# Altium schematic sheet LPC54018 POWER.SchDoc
size A4; CheckedBy: 赵金生; Author: 伍伟业; CompanyName: 广州周立功单片机科技有限公司; DocumentNumber: 8; SheetNumber: 8A; SheetTotal: 19; PageSetup: Record=PageOptions|CenterHorizontal=True|CenterVertical=True|PrintScale=1.00|XCorrection=1.00|YCorrection=1.00|PrintKind=0|BorderSize=5000000|LeftOffset=0|BottomOffset=0|Orientation=2|PaperLength=1000|PaperWidth=1000|Scale=100|PaperSource=7|PrintQuality=600|MediaType=1|DitherType=10|PaperKind=A4|PrintScaleMode=1; DesignDate: 2017-3-16; CheckDate: 2017-3-16; SheetName: LPC54018 POWER; SheetVersion: V1.0; SheetDescription: LPC54018 POWER; ModifiedDate1: 2017/8/15; ModifiedContent1: 复位电路增加续流二极管D12
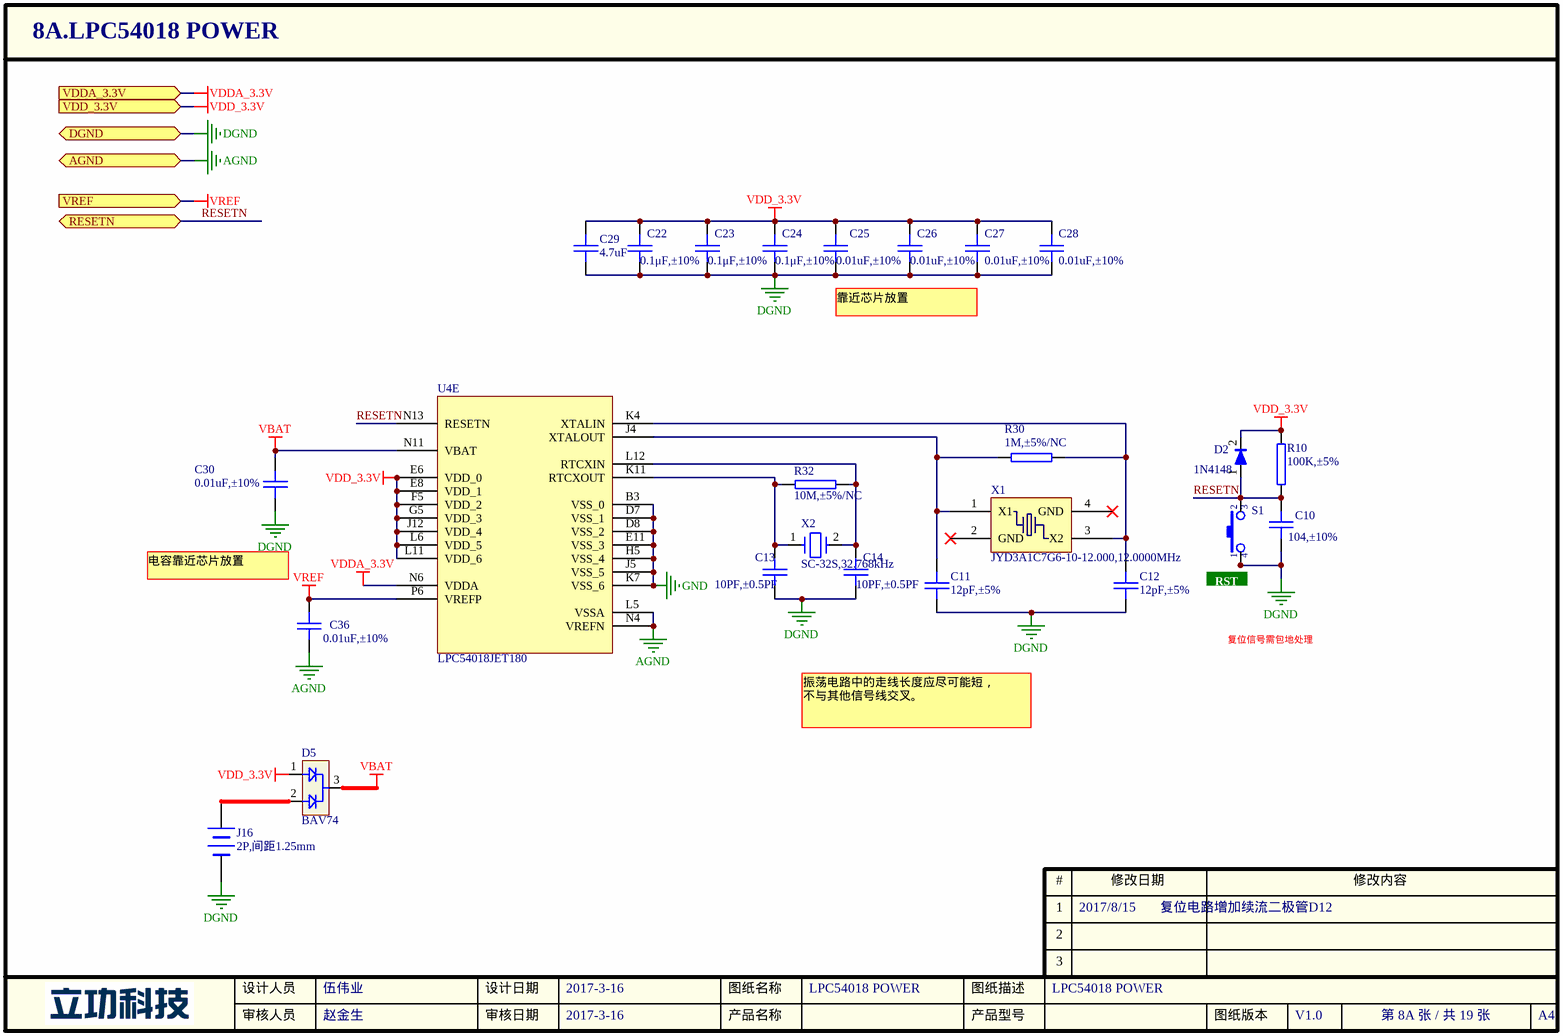
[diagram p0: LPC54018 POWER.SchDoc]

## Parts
C10  104,±10%  [0603C]
C11  12pF,±5%  [0402C]
C12  12pF,±5%  [0402C]
C13  10PF,±0.5PF  [0402C]
C14  10PF,±0.5PF  [0402C]
C22  0.1μF,±10%  [0402C]
C23  0.1μF,±10%  [0402C]
C24  0.1μF,±10%  [0402C]
C25  0.01uF,±10%  [0402C]
C26  0.01uF,±10%  [0402C]
C27  0.01uF,±10%  [0402C]
C28  0.01uF,±10%  [0402C]
C29  4.7uF  [0603CL]
C30  0.01uF,±10%  [0402C]
C36  0.01uF,±10%  [0402CL]
D2  1N4148  [SOD-323]
D5  BAV74  [SOT-23]
J16  value 2P,间距1.25mm  [FPC2-49T]  (hidden comment: BATTERY)
R10  100K,±5%  [0402R]
R30  1M,±5%/NC  [0402R]
R32  10M,±5%/NC  [0402R]
S1  TS0641-0501B,6×6×5.0mm  [KEY-6S]  (value not drawn)
U4  LPC54018JET180  [BGA180C80P14x14]  (part E of 5)
X1  JYD3A1C7G6-10-12.000,12.0000MHz  [OSCCC250X320X80-4N]
X2  SC-32S,32.768kHz  [XTAL320X150X90]

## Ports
AGND, DGND, RESETN (bidir), VDD_3.3V (in), VDDA_3.3V (in), VREF (in)

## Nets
AGND: C36.2 U4.L5(VSSA) U4.N4(VREFN) ; port AGND
DGND: C10.2 C11.2 C12.1 C13.2 C14.2 C22.2 C23.2 C24.2 C25.2 C26.2 C27.2 C28.2 C29.2 C30.2 J16.2(-) S1.1 S1.4 ; port DGND
GND: U4.B3(VSS_0) U4.D7(VSS_1) U4.D8(VSS_2) U4.E11(VSS_3) U4.H5(VSS_4) U4.J5(VSS_5) U4.K7(VSS_6)
VBAT: C30.1 D5.3(A) U4.N11(VBAT)
VDD_3.3V: C22.1 C23.1 C24.1 C25.1 C26.1 C27.1 C28.1 C29.1 D2.2 D5.1(D1) R10.2 U4.E6(VDD_0) U4.E8(VDD_1) U4.F5(VDD_2) U4.G5(VDD_3) U4.J12(VDD_4) U4.L6(VDD_5) U4.L11(VDD_6) ; port VDD_3.3V
VDDA_3.3V: U4.N6(VDDA) ; port VDDA_3.3V
VREF: C36.1 U4.P6(VREFP) ; port VREF
RESETN: C10.1 D2.1 R10.1 S1.2 S1.3 U4.N13(RESETN) ; port RESETN
NetC11_1: C11.1 R30.1 U4.J4(XTALOUT) X1.1(X1)
NetC12_2: C12.2 R30.2 U4.K4(XTALIN) X1.3(X2)
NetC13_1: C13.1 R32.1 U4.K11(RTCXOUT) X2.1
NetC14_1: C14.1 R32.2 U4.L12(RTCXIN) X2.2
NetD5_2: D5.2(D2) J16.1(+)

Not connected (* = marked no-connect by the designer): X1 2(GND)* 4(GND)*

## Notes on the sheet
- 靠近芯片放置
- 电容靠近芯片放置
- (near S1) RST
- 复位信号需包地处理
- 振荡电路中的走线长度应尽可能短，
  不与其他信号线交叉。

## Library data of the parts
C10 = 1.02.01.0032: 104,±10%,50V,X7R,0603,*,RoHS; 名称: 电容; 封装: 0603; 设备封装名称: C0603_104_X7R_50V_10%; 厂商: muRata; 贴片和直插: SMT; 器件优选方案: 正常状态，可以选用
C11 C12 = 1.02.17.0018: GRM1555C1H120JA01D,12pF,±5%,50V,C0G,0402,muRata,RoHS; 名称: 电容; 封装: 0402; 设备封装名称: C0402_12PF_COG_50V_5%; 贴片和直插: SMT; 器件优选方案: 正常状态，可以选用
C13 C14 = 1.02.17.0008: GRM1555C1H100JA01D,10PF,±0.5PF,50V,COG,0402,muRata,RoHS; 名称: 电容; 封装: 0402; 贴片和直插: SMT; 器件优选方案: 正常状态，可以选用; 设备封装名称: C0402_10PF_COG_50V_+-0.5PF
C22-C24 = 1.02.17.0006: GRM155R71C104KA88D,0.1μF,±10%,16V,X7R,0402,muRata,RoHS; 名称: 电容; 封装: 0402; 设备封装名称: C0402_0.1uF_X7R_16V_10%; 贴片和直插: SMT; 器件优选方案: 正常状态，可以选用
C25-C28 C30 C36 = 1.02.17.0019: GRM155R71H103KA88D,0.01uF,±10%,50V,X7R,0402,muRata,RoHS; 名称: 电容; 封装: 0402; 设备封装名称: C0402_0.01uF_X7R_50V_10%; 贴片和直插: SMT; 器件优选方案: 正常状态，可以选用
C29 = 1.02.01.0080: GRM188R61A475KE15D,4.7uF,±10%,10V,X5R,0603,muRata,RoHS; 名称: 电容; 封装: 0603; 贴片和直插: SMT; PCB备注: 160602yjh; 器件优选方案: 正常状态，可以选用
D2 = 1.04.07.0027: 1N4148,SOD-323,长电,RoHS; 名称: 二极管; 设备封装名称: SOD-323_1N4148; 贴片和直插: SMT; 器件优选方案: 正常状态，可以选用
D5 = 1.04.07.0013: BAV74,SOT-23,,RoHS; 名称: 双二极管; 设备封装名称: SOT-23_BAV74; 贴片和直插: SMT; 器件优选方案: 正常状态，可以选用
J16 = 1.10.05.0096: 2P,间距1.25mm,Wafer凹槽边框,90°,FPC2-49T; 名称: 插座; 贴片和直插: SMT
R10 = 1.01.17.0047: 100K,±5%,0402,RALEC,RoHS; 名称: 电阻; 封装: 0402; 设备封装名称: R0402_100K; 贴片和直插: SMT; 器件优选方案: 正常状态，可以选用
R30 = 1.01.17.0013: 1M,±5%,0402,RALEC,RoHS; 名称: 电阻; 封装: 0402; 设备封装名称: R0402_1M; 型号: 1M,±5%; 贴片和直插: SMT; 器件优选方案: 正常状态，可以选用
R32 = 1.01.17.0005: 10M,±5%,0402,RALEC,RoHS; 名称: 电阻; 封装: 0402; 设备封装名称: R0402_10M; 型号: 10M,±5%; 贴片和直插: SMT; 器件优选方案: 正常状态，可以选用
S1 = 1.09.01.0003: TS0641-0501B,6×6×5.0mm,黑色,SMD,卷带装,RoHS; 名称: 轻触开关; 贴片和直插: SMT; 器件优选方案: 正常状态，可以选用
U4 = 1.05.02.0192: LPC54018JET180,TFBGA180,NXP,RoHS; 名称: 集成电路; 贴片和直插: SMT; PCB备注: 170811LMD重补; 器件优选方案: 正常状态，可以选用
X1 = 1.07.01.0032: JYD3A1C7G6-10-12.000,12.0000MHz,±10ppm,10pF,-40~85℃,±10ppm,SMD3225,*,JYEG,RoHS; 名称: 晶体; 贴片和直插: SMT; PCB备注: 151229lmd171128ZW; 器件优选方案: 正常状态，可以选用
X2 = 1.07.02.0056: SC-32S,32.768kHz,12.5pF,±20ppm,SMD3215,SII,RoHS; 名称: 晶振; 贴片和直插: SMT; PCB备注: 171129ZW; 器件优选方案: 正常状态，可以选用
